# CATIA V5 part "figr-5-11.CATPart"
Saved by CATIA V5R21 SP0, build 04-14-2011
Part number: Part1
Bounding box of the stored display mesh (mm): x 0 to 150, y -70 to 70, z -150 to 69.804
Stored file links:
  D:\CATIA V5R21 E-RESOURCES\CATIA-V5R21\catia-v5r21-prt\c05-catia-v5r20-prt\catia-v5r21-figr-5-11.CATPart
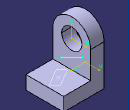
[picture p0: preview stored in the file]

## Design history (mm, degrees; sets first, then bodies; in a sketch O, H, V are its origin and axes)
Set1
  Sketch1 on face of Pad2, origin (0, 0, -100), H (1, 0, 0), V (0, 1, 0)
    point P1 (100, 0)
    coincidence: P1 H
  Sketch2 on face of Pad1, origin (50, 0, 0), H (0, 1, 0), V (0, 0, 1)
    line L1 (-40, -80) -> (40, -40)
  Plane1: type 1Line1Pt, RefPoint Sketch1, Line Sketch2
Body1 (main body)
  Sketch3 on yz-plane, origin (0, 0, 0), H (0, 1, 0), V (0, 0, 1)
    arc A1 centre (0, 0) radius 70 from (70, 0) to (-70, 0) ccw
    point P1 (70, 0)
    point P2 (-70, 0)
    line L1 (-70, 0) -> (-70, -150)
    line L2 (-70, -150) -> (70, -150)
    line L3 (70, -150) -> (70, 0)
    circle A2 centre (0, 0) radius 37.5
    radius A1 = 70
    radius A2 = 37.5
    distance O L2 = 150
    coincidence: P1 H, P2 H
    tangency: L1 A1, L3 A1
    horizontal: L2 H
  Pad1: profile Sketch3, direction (1, 0, 0), length 50
  Sketch4 on face of Pad1, origin (50, 0, 0), H (0, 1, 0), V (0, 0, 1)
    line L1 (-70, -150) -> (70, -150)
    line L2 (70, -150) -> (70, -100)
    line L3 (70, -100) -> (-70, -100)
    line L4 (-70, -100) -> (-70, -150)
    reference projected line E1 (-70, -150) -> (70, -150) from edge [face of Pad1 | face of Pad1]
    reference projected line E2 (-70, 0) -> (-70, -150) from edge [face of Pad1 | face of Pad1]
    reference projected line E3 (70, -150) -> (70, 0) from edge [face of Pad1 | face of Pad1]
    length L2 = 50
    horizontal: L1 H, L3 H
    vertical: L2 V, L4 V
    coincidence: L1 E1, E2 L4, L2 E3
  Pad2: profile Sketch4, direction (1, 0, 0), length 100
